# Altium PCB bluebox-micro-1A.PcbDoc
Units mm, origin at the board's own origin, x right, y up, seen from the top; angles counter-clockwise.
Board outline 61.47 x 18.68 mm, 4 copper layers (Top Layer, Internal Plane 1, Mid-Layer 2, Bottom Layer), stack 0.859 mm thick; 97 components, 77 nets, 309 pads, 136 vias.
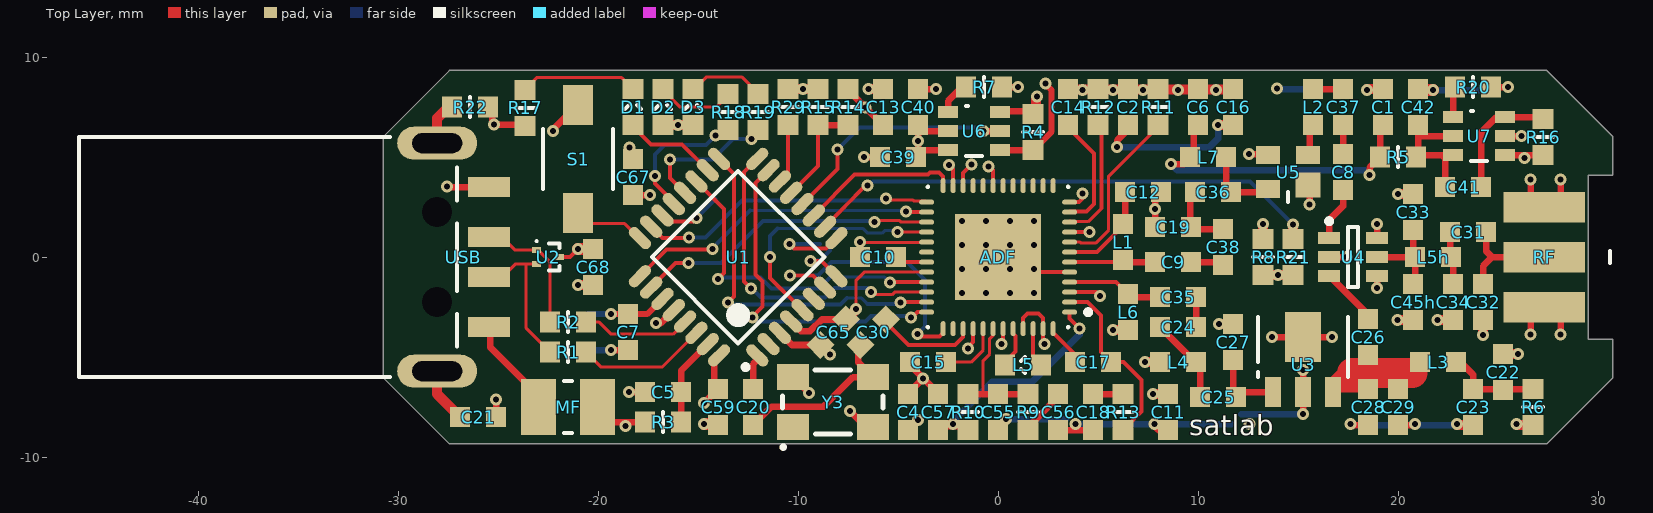
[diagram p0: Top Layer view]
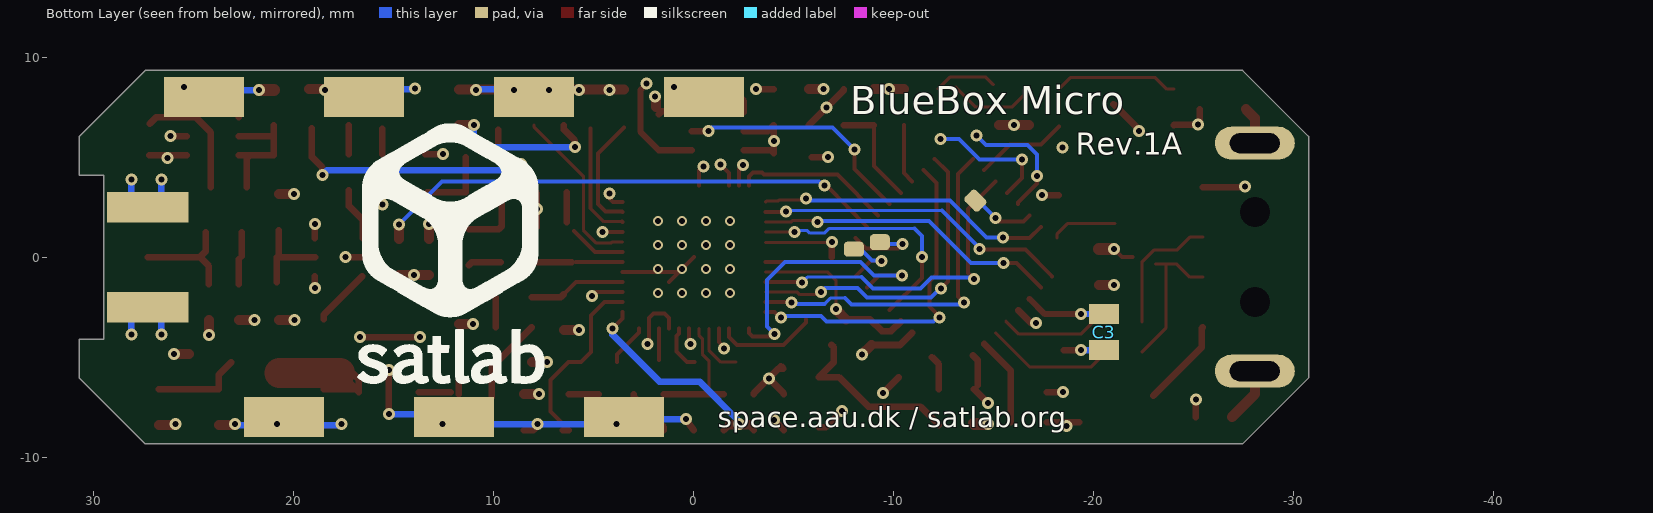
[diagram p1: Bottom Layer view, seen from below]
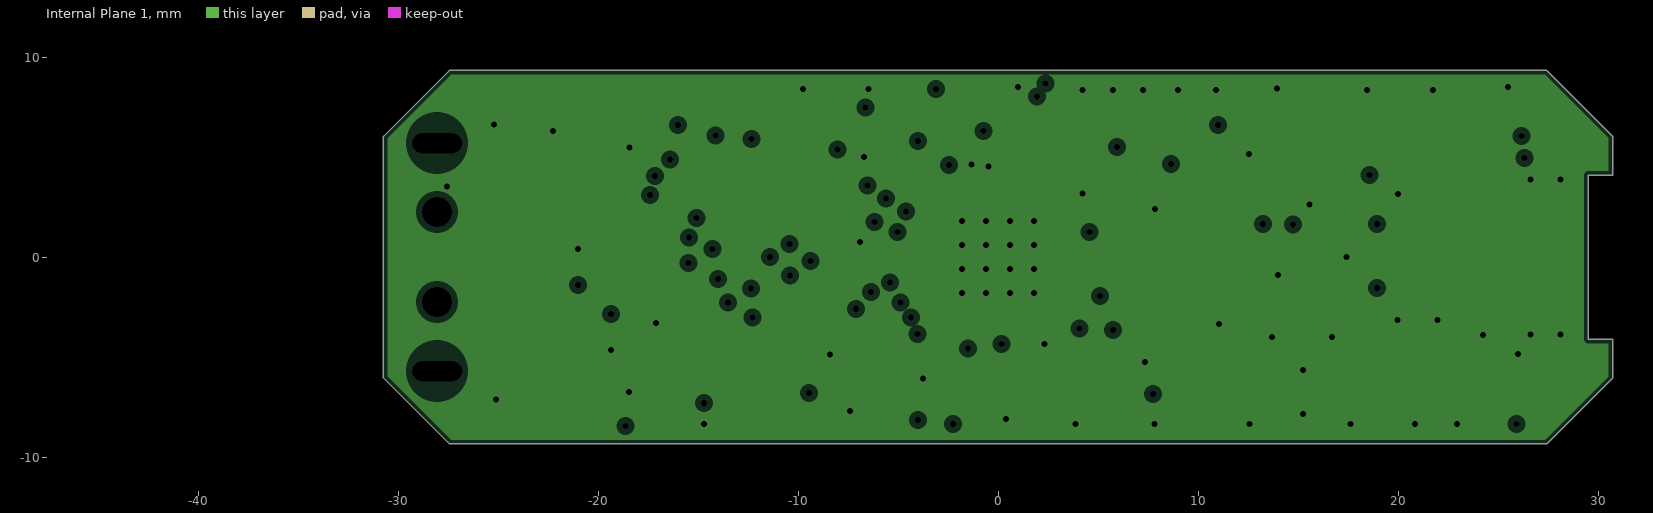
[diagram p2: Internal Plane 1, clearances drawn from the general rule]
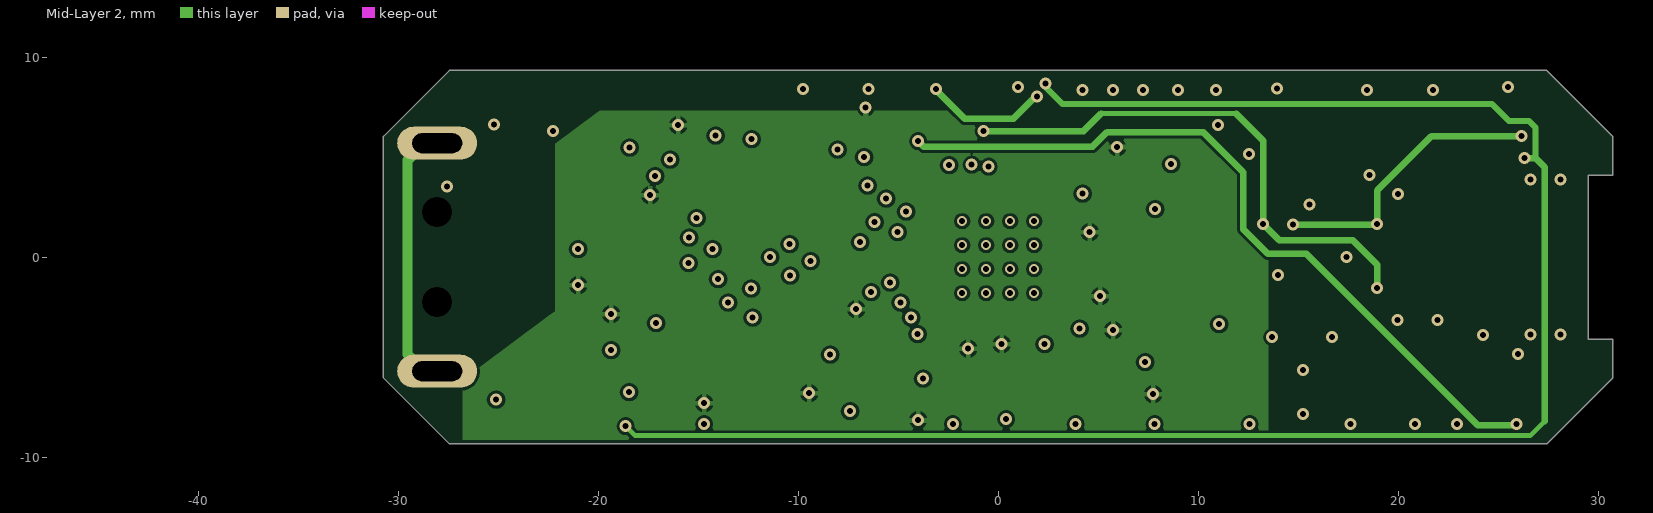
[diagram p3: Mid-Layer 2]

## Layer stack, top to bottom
Top Layer: signal copper 0.0356
Dielectric: core 0.1981, FR-4, Dk 3.6
Internal Plane 1: plane copper 0.0356, net GND
Dielectric: prepreg 0.32, FR-4, Dk 4.8
Mid-Layer 2: signal copper 0.0356
Dielectric: core 0.1981, FR-4, Dk 3.6
Bottom Layer: signal copper 0.0356

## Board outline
-27.434,-9.34 -30.734,-6.04 -30.734,6.04 -30.732,6.04 -27.434,9.338 -27.434,9.34 27.434,9.34 30.734,6.04 30.734,4.1 29.5,4.1 29.5,-4.1 30.734,-4.1 30.734,-6.04 27.434,-9.34

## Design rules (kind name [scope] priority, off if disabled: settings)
Clearance [All] p1: gap=0.15
MinimumSolderMaskSliver [All] p1: minsoldermaskwidth=0.075
PlaneClearance [All] p1: clearance=0.3
PlaneConnect [All] p1: planeconnectstyle=Relief reliefexpansion=0.15 reliefentries=4 reliefconductorwidth=0.254 reliefairgap=0.15
PolygonConnect [All] p1: connectstyle=Relief reliefconductorwidth=0.254 reliefentries=4 polygonreliefangle="90 Angle"
RoutingVias [All] p1: holewidth=0.3 width=0.5 viastyle="Through Hole" minholewidth=0.3 minwidth=0.5 maxholewidth=3 maxwidth=2
SilkscreenOverComponentPads [All] p1: minsilkscreentomaskgap=0.154
SolderMaskExpansion [All] p1: expansion=0.075
Width [All] p1: maxlimit=2 minlimit=0.15 preferedwidth=0.2
24 further rules are at their usual default settings.

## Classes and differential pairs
component class transceiver: ADF C3 C4 C9 C9h C10 C11 C12 C12h C13 C14 C15 C16 C17 C18 C20 C30 C35 C42h C55 C56 C57 C59 L1 L1h L5 L6 R9 R10 R11 R12 R13 Y3
component class mcu: C2 C5 C7 C21 C60 C61 C62 C63 C64 C65 C67 C68 CaSS9 D1 D2 D3 MF Q4 R1 R2 R3 R14 R15 R17 R18 R19 R22 R29 R34 S1 U1 U2 USB Usw9 VR1
component class misc_rf: C1 C6 C8 C19 C22 C23 C24 C25 C26 C27 C28 C29 C31 C32 C33 C34 C36 C37 C38 C39 C40 C41 C42 C45h C? L2 L3 L4 L5h L7 L? Q2 R4 R5 R6 R7 R8 R16 R20 R21 R? RF U3 U4 U5 U6 U7 U?

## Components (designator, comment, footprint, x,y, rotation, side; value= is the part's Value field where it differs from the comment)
ADF "ADF7021" QFN50P700X700X100-48M 0,0 r180 top
C1 "Cap Semi" C06#1 19.25,7.5 r90 top
C2 "Capacitor" C06#1 6.5,7.5 r270 top
C3 "Cap Semi" C06#2 -20.5,-3.75 r90 bottom
C4 "Cap Semi" C06#1 -4.5,-7.75 r270 top
C5 "Cap Semi" C06#1 -16.75,-6.75 r0 top
C6 "Cap Semi" C06#1 10,7.5 r90 top
C7 "Cap Semi" C06#1 -18.5,-3.75 r270 top
C8 "Cap Semi" C06#1 17.25,4.25 r90 top
C9 "Cap Semi" C06#1 8.75,-0.25 r180 top
C10 "Cap Semi" C06#1 -6,0 r0 top
C11 "Cap Semi" C06#1 8.5,-7.75 r90 top
C12 "Cap Semi" C06#1 7.25,3.25 r180 top
C13 "Cap Semi" C06#1 -5.75,7.5 r270 top
C14 "Cap Semi" C06#1 3.5,7.5 r270 top
C15 "Cap Semi" C06#1 -3.5,-5.25 r0 top
C16 "Cap Semi" C06#1 11.75,7.5 r270 top
C17 "Cap Semi" C06#1 4.75,-5.25 r180 top
C18 "Cap Semi" C06#1 4.75,-7.75 r270 top
C19 "Cap Semi" C06#1 8.75,1.5 r180 top
C20 "Cap Semi" C06#1 -12.25,-7.5 r90 top
C21 "Cap Semi" C06#1 -26,-8 r0 top
C22 "Cap Semi" C06#1 25.25,-5.75 r90 top
C23 "Cap Semi" C06#1 23.75,-7.5 r270 top
C24 "Cap Semi" C06#1 9,-3.5 r180 top
C25 "Cap Semi" C06#1 11,-7 r0 top
C26 "Cap Semi" C06#1 18.5,-4 r270 top
C27 "Cap Semi" C06#1 11.75,-4.25 r270 top
C28 "Cap Semi" C06#1 18.5,-7.5 r270 top
C29 "Cap Semi" C06#1 20,-7.5 r270 top
C30 "Cap Semi" C06#1 -6.25,-3.75 r45 top
C31 "Capacitor" C06#1 23.5,1.25 r180 top
C32 "Capacitor" C06#1 24.25,-2.25 r90 top
C33 "Cap Semi" C06#1 20.75,2.25 r90 top
C34 "Cap Semi" C06#1 22.75,-2.25 r270 top
C35 "Cap Semi" C06#1 9,-2 r0 top
C36 "Cap Semi" C06#1 10.75,3.25 r0 top
C37 "Cap Semi" C06#1 17.25,7.5 r90 top
C38 "Cap Semi" C06#1 11.25,0.5 r270 top
C39 "Capacitor" C06#1 -5,5 r0 top
C40 "Capacitor" C06#1 -4,7.5 r90 top
C41 "Capacitor" C06#1 23.25,3.5 r0 top
C42 "Capacitor" C06#1 21,7.5 r270 top
C45h "Cap Semi" C06#1 20.75,-2.25 r90 top
C55 "Cap Semi" C06#1 0,-7.75 r90 top
C56 "Cap Semi" C06#1 3,-7.75 r90 top
C57 "Cap Semi" C06#1 -3,-7.75 r270 top
C59 "Cap Semi" C06#1 -14,-7.5 r90 top
C65 "Capacitor" C06#1 -8.25,-3.75 r45 top
C67 "Capacitor" C06#1 -18.25,4 r270 top
C68 "Capacitor" C06#1 -20.25,-0.5 r270 top
D1 "LED" L06 -18.25,7.5 r90 top
D2 "LED" L06 -16.75,7.5 r90 top
D3 "LED" L06 -15.25,7.5 r90 top
L1 "Inductor" C06#1 6.25,0.75 r270 top
L2 "Inductor" C06#1 15.75,7.5 r90 top
L3 "Inductor" C06#1 22,-5.25 r0 top
L4 "Inductor" C06#1 9,-5.25 r0 top
L5 "Inductor" L06 1.245,-5.385 r180 top
L5h "Inductor" C06#1 21.75,0 r0 top
L6 "Inductor" C06#1 6.5,-2.75 r270 top
L7 "Inductor" C06#1 10.5,5 r180 top
MF "CapacitorBig" C1210 -21.5,-7.5 r180 top
R1 "Resistor" R06 -21.5,-4.75 r180 top
R2 "Resistor" R06 -21.5,-3.25 r0 top
R3 "Resistor" R06 -16.75,-8.25 r0 top
R4 "Resistor" R06 1.75,6.25 r270 top
R5 "Resistor" R06 20,5 r0 top
R6 "Resistor" R06 26.75,-7.5 r270 top
R7 "Resistor" R06 -0.7,8.5 r180 top
R8 "Resistor" R06 13.25,0 r90 top
R9 "Res Semi" R06 1.5,-7.75 r90 top
R10 "Res Semi" R06 -1.5,-7.75 r90 top
R11 "Res Semi" R06 8,7.5 r90 top
R12 "Res Semi" R06 5,7.5 r270 top
R13 "Res Semi" R06 6.25,-7.75 r90 top
R14 "Resistor" R06 -7.5,7.5 r90 top
R15 "Resistor" R06 -9,7.5 r270 top
R16 "Resistor" R06 27.25,6 r270 top
R17 "Resistor" R06 -23.647,7.468 r90 top
R18 "Resistor" R06 -13.5,7.25 r90 top
R19 "Resistor" R06 -12,7.25 r90 top
R20 "Resistor" R06 23.75,8.5 r180 top
R21 "Resistor" R06 14.75,0 r90 top
R22 "Resistor" R06 -26.4,7.5 r0 top
R29 "Resistor" R06 -10.5,7.5 r270 top
RF "50 Ohm - Linx CONSMA003.062" SMA-EGDE 29.3,0 r0 top
S1 "434123050816" spsd-raised -21,4.9 r270 top
U1 "ATmega32U2-AU" 32A_L -13,0 r135 top
U2 "TPD2EUSB30ADRTR" DRT3 -22.5,0 r270 top
U3 "MGA-31589" SOT-223B-SMALL 15.25,-4.5 r0 top
U4 "AS193-73" SOT95P280X145-6N 17.75,0 r0 top
U5 "MBC13916" MBC13916 14.5,4.25 r90 top
U6 "FDC6329L" SSOT-6 -2.5,7.25 r0 top
U7 "FDC6329L" SSOT-6 22.75,7 r0 top
USB "1470695-2" 1470695A -30.75,0 r180 top
Y3 "FOX924B" FOX924 -10.25,-6 r0 top

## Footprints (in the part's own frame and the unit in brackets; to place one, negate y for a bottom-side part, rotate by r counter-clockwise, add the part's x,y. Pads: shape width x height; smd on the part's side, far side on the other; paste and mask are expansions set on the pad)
32A_L [mm] "Thin QFP, 32-Leads, Body 7x7mm, Pitch 0.8mm, IPC High Density"
  oval 1.35x0.55 smd: 1(-4.15,2.8) 2(-4.15,2) 3(-4.15,1.2) 4(-4.15,0.4) 5(-4.15,-0.4) 6(-4.15,-1.2) 7(-4.15,-2) 8(-4.15,-2.8) 17(4.15,-2.8) 18(4.15,-2) 19(4.15,-1.2) 20(4.15,-0.4) 21(4.15,0.4) 22(4.15,1.2) 23(4.15,2) 24(4.15,2.8)
  oval 0.55x1.35 smd: 9(-2.8,-4.15) 10(-2,-4.15) 11(-1.2,-4.15) 12(-0.4,-4.15) 13(0.4,-4.15) 14(1.2,-4.15) 15(2,-4.15) 16(2.8,-4.15) 25(2.8,4.15) 26(2,4.15) 27(1.2,4.15) 28(0.4,4.15) 29(-0.4,4.15) 30(-1.2,4.15) 31(-2,4.15) 32(-2.8,4.15)
  silkscreen extent -4.27,-3.05 3.05,3.75, body extent -3.5,-3.5 3.5,3.5, height 1.2
1470695A [mm] "Connector; USB1.1, Type A, SM; 4 Position; Right Angle"
  rect 2.1x1 smd: 1(-5.3,3.5) 2(-5.3,1) 3(-5.3,-1) 4(-5.3,-3.5)
  oval 4x1.65 hole 1 slot 2.5 at 0 deg: 5(-2.7,-5.7) 6(-2.7,5.7)
  round 1.2 hole 1.5 unplated: MH1(-2.7,-2.25) MH2(-2.7,2.25)
  silkscreen extent -3.7,-6 15.2,6
C06#1 [mm] "Chip Capacitor, 2-Leads, Body 1.6x0.8mm, IPC Low Density"
  rect 1x1 smd: 1(-0.9,0) 2(0.9,0)
  body extent -0.8,-0.41 0.8,0.41, height 0.82
C06#2 [mm] "Chip Capacitor, 2-Leads, Body 1.6x0.8mm, IPC Low Density"
  rect 1x1.5 smd: 1(-0.9,0) 2(0.9,0)
  body extent -0.8,-0.41 0.8,0.41, height 0.82
C1210 [mm] "Chip Capacitor, 2-Leads, Body 3.2x2.5mm, IPC Low Density"
  rect 1.75x2.8 smd: 1(-1.475,0) 2(1.475,0)
  silkscreen extent -0.2,-1.3 0.2,1.3, body extent -1.75,-1.35 1.75,1.35, height 2.7
DRT3 [mm] "SOTFL, 3-Leads, Body 1x1mm (inc leads), Pitch 0.35mm"
  rect 0.3x0.45 smd: 1(-0.35,-0.575) 2(0.35,-0.575) 3(0,0.575)
  silkscreen extent -0.85,-0.62 0.67,0.58, body extent -0.52,-0.42 0.52,0.42, height 0.5
FOX924 [mm]
  rect 1.6x1.3 smd: 1(0,-2.5) 2(4,-2.5) 3(4,0) 4(0,0)
  silkscreen extent -0.56,-3.56 4.5,0.35, body extent -0.53,-2.83 4.5,0.35, height 1.5
L06 [mm] "Chip LED, 2-Leads, Body 1.6x0.8mm, IPC Low Density"
  rect 1x1.05 smd: 1(-0.9,0) 2(0.9,0)
  silkscreen extent -0.1,-0.4 0.1,0.4, body extent -0.85,-0.45 0.85,0.45, height 0.9
MBC13916 [mm] "SOT-143; 4 Leads; FOR LNA"
  rect 1.25x1.25 smd: 1(-0.65,-1)
  rect 0.9x1.2 smd: 2(0.85,-1) 3(0.85,1) 4(-0.85,1)
  silkscreen extent -1.5,0 -1,0
QFN50P700X700X100-48M [mm] "QFN, 48-Leads, Body 7,0x7,0mm (max), Pitch 0,50mm, IPC Low Density"
  oval 0.75x0.25 smd mask+0.154: 1(-3.575,2.75) 2(-3.575,2.25) 3(-3.575,1.75) 4(-3.575,1.25) 5(-3.575,0.75) 6(-3.575,0.25) 7(-3.575,-0.25) 8(-3.575,-0.75) 9(-3.575,-1.25) 10(-3.575,-1.75) 11(-3.575,-2.25) 12(-3.575,-2.75) 25(3.575,-2.75) 26(3.575,-2.25) 27(3.575,-1.75) 28(3.575,-1.25) 29(3.575,-0.75) 30(3.575,-0.25) 31(3.575,0.25) 32(3.575,0.75) 33(3.575,1.25) 34(3.575,1.75) 35(3.575,2.25) 36(3.575,2.75)
  oval 0.25x0.75 smd mask+0.154: 13(-2.75,-3.575) 14(-2.25,-3.575) 15(-1.75,-3.575) 16(-1.25,-3.575) 17(-0.75,-3.575) 18(-0.25,-3.575) 19(0.25,-3.575) 20(0.75,-3.575) 21(1.25,-3.575) 22(1.75,-3.575) 23(2.25,-3.575) 24(2.75,-3.575) 37(2.75,3.575) 38(2.25,3.575) 39(1.75,3.575) 40(1.25,3.575) 41(0.75,3.575) 42(0.25,3.575) 43(-0.25,3.575) 44(-0.75,3.575) 45(-1.25,3.575) 46(-1.75,3.575) 47(-2.25,3.575) 48(-2.75,3.575)
  rect 4.3x4.3 smd mask+0.154: 49(0,0)
  silkscreen extent -4.62,-3.53 3.53,3.52, body extent -3.5,-3.5 3.5,3.5, height 1
R06 [mm] "Chip Resistor, 2-Leads, Body 1.6x0.8mm, IPC Low Density"
  rect 1x1.05 smd: 1(-0.9,0) 2(0.9,0)
  silkscreen extent 0,-0.5 0,0.5, body extent -0.8,-0.4 0.8,0.4, height 0.55
SMA-EGDE [mm] "Linx CONSMA003.062"
  rect 4.06x1.52 smd: 1(-2,-2.5) 1(-2,2.5) 2(-2,0)
  rect 4.06x1.52 smd far side: 1(-2,-2.5) 1(-2,2.5)
  silkscreen extent 1.3,-0.3 1.3,0.3
SOT95P280X145-6N [mm] "SOT23, 6-Leads, Body 3,0x3,0mm (max), Pitch 0,95mm, IPC Medium Density"
  rect 1.1x0.6 smd: 1(-1.2,0.95) 2(-1.2,0) 3(-1.2,-0.95) 4(1.2,-0.95) 5(1.2,0) 6(1.2,0.95)
  silkscreen extent -1.32,-1.5 0.25,1.92, body extent -0.87,-1.52 0.87,1.53, height 1.45
SOT-223B-SMALL [mm] "used for PA in bluebox micro"
  rect 0.8x1.5 smd: 1(-1.5,-2.25) 2(0,-2.25) 3(1.5,-2.25)
  rect 1.8x2.5 smd: 4(0,0.5)
  silkscreen extent -2.25,-1.5 2.25,1.5
spsd-raised [mm] "WURTH ELEKTRONIK - 434123050816 - SWITCH, 160GF, 6X3.5X5MM, BLK, J-BEND"
  rect 2x1.5 smd: 1(2.7,0) 2(-2.7,0)
  silkscreen extent -1.5,-1.75 1.5,1.75
SSOT-6 [mm]
  rect 1x0.6 smd: 1(0,0) 2(0,-0.95) 3(0,-1.9) 4(2.6,-1.9) 5(2.6,-0.95) 6(2.6,0)
  silkscreen extent 0.9,-2.2 1.7,0.3

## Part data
ADF: "ADF7021 transceiver"
C1 C3 C4 C5 C6 C7 C8 C9 C10 C11 C12 C13 C14 C15 C16 C17 C18 C19 C20 C21 C22 C23 C24 C25 C26 C27 C28 C29 C30 C33 C34 C35 C36 C37 C38 C45h C55 C56 C57 C59: "Capacitor (Semiconductor SIM Model)"
C2 C31 C32 C39 C40 C41 C42 C65 C67 C68: "Capacitor, standard"
D1 D2 D3: "Typical RED GaAs LED"
MF: "Capacitor for PRU etc."
R9 R10 R11 R12 R13: "Semiconductor Resistor"
RF: library part SMA_BOARD_EGDE, "Linx CONSMA003.062  -  SMA Female Edge Mount for 1.6 mm PCB"
S1: library part spsd-raised, "Switch, Subminiature SMT, WURTH ELEKTRONIK - 434123050816 - SWITCH, 160GF, 6X3.5X5MM, BLK, J-BEND"
U1: "8-bit AVR Microcontroller, 2.7-5.5V, 32KB Flash, 1KB EEPROM, 1KB SRAM, 32-pin TQFP, Industrial Grade (-40°C to 85°C)"
U2: "ESD / Surge Solution for High Speed, Low Voltage Interface, 2 Channels, -40 to +85 degC, 3-pin SOT (DRT), Green (RoHS & no Sb/Br)"
U3: "0.5 W High Gain Driver Amplifier"
U4: "PHEMT GaAs IC High-Linearity 3 V  Control SPDT Switch 0.1–2.5 GHz"
U6 U7: "Integrated Load Switch"
USB: "USB 1.1, Right Angle, SMT, A Type, Plug, 4 Position, Natural"
Y3: "FOX924B TCXO 19.44 MHz"

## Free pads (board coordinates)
  rrect50% 1x0.8 smd far side rot 45: 0(-14.075,2.825)
  rrect50% 1x0.8 smd far side: 0(-9.3,0.75)
  rect 4x2 smd far side: 0(-0.5,8) 0(3.5,-8) 0(8,8) 0(12,-8) 0(16.5,8) 0(20.5,-8) 0(24.5,8)
  rrect50% 1x0.75 smd far side: 1(-8,0.4)

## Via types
v1: diameter 0.6, hole 0.3, Top Layer to Bottom Layer, 43 vias
v2: diameter 0.6, hole 0.3, Top Layer to Bottom Layer, tented top, 34 vias
v3: diameter 0.6, hole 0.3, Top Layer to Bottom Layer, tented bottom, 22 vias
v4: diameter 0.6, hole 0.3, Top Layer to Bottom Layer, tented both sides, 21 vias
v5: diameter 0.5, hole 0.3, Top Layer to Bottom Layer, tented top, 16 vias

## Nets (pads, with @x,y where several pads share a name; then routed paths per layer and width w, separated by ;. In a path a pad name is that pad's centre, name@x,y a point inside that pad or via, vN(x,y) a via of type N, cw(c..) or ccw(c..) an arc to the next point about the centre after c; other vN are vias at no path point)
C-RX: R21.2 U1.10 U4.6 U7.5 | length 41.7
  Top Layer w0.2: U1.10 -6.647,3.55 v1@-6.5,3.55
  Top Layer w0.34: U4.6 v3(18.95,1.65) ; U7.5 v2(26.175,6.05)
  Top Layer w0.5: R21.2 v3(14.75,1.625)
  Mid-Layer 2 w0.34: v3(14.75,1.625) v3@18.925,1.625 ; v3(18.95,1.65) 18.95,3.325 21.675,6.05 v2(26.175,6.05)
  Bottom Layer w0.2: v1@-6.5,3.55 -6.35,3.675 -6.25,3.775 12.6,3.775 v3(14.75,1.625)
  other v1: -6.525,3.575
C-TX: R8.2 U1.12 U4.4 U6.5 | length 40.2
  Top Layer w0.2: U1.12 -8.025,4.409 v1(-8.025,5.375)
  Top Layer w0.34: v2(-0.725,6.3) U6.5 ; v4(18.95,-1.55) U4.4
  Top Layer w0.5: R8.2 v3(13.25,1.65)
  Mid-Layer 2 w0.25: 5.15,7.175 11.9,7.175
  Mid-Layer 2 w0.34: v2(-0.725,6.3) 4.275,6.3 5.15,7.175 ; 11.9,7.175 13.25,5.825 v3(13.25,1.65) 14.05,0.85 17.725,0.85 18.95,-0.375 v4(18.95,-1.55)
  Bottom Layer w0.2: v1(-8.025,5.375) -6.925,6.475 -0.9,6.475 v2(-0.725,6.3)
CE: ADF.24 U1.11 | length 8.3
  Top Layer w0.2: U1.11 -7.178,4.125 -3.5,4.125 -3.4,4.225 -2.95,4.225 -2.75,4.025 ADF.24 -2.75,4
CLK_OUT: ADF.36 U1.15 | length 16.9
  Top Layer w0.2: v1@-12.25,-2.875 -12.175,-2.875 -11.775,-2.475 -11.775,-1.225 -12.125,-0.875 -12.125,3.703 U1.15 ; v2@-4.35,-3 -4.275,-3 -4.025,-2.75 ADF.36
  Bottom Layer w0.2: v1@-12.275,-2.9 -12.275,-2.925 -11.975,-3.225 -6.625,-3.225 -6.35,-2.95 v2@-4.375,-2.95
  other v1: -12.275,-3.025
  other v2: -4.35,-3.025
CPOUT: ADF.42 C55.2 R9.2 R10.2 | length 6.5
  Top Layer w0.15: -0.75,-6.85 -0.75,-5.175 -0.425,-4.85 -0.425,-4.075 -0.25,-3.9 ADF.42
  Top Layer w0.34: R10.2 R9.2
CREG3: ADF.41 C15.2 | length 2.7
  Top Layer w0.15: -2.1,-5.25 -1.35,-5.25 -0.75,-4.65 ADF.41
D+: R2.1 U2.1 USB.3 | length 6.6
  Top Layer w0.15: USB.3 -24.8,1 -24.15,0.35 -23,0.35 -22.4,-0.25 R2.1
D-: R1.2 U2.2 USB.2 | length 7.5
  Top Layer w0.15: USB.2 -24.8,-1 -24.15,-0.35 U2.2 ; -23.6,-0.35 -23.6,-3.55 R1.2
DATA_CLK: ADF.35 U1.17 | length 17.9
  Top Layer w0.2: U1.17 -13.2,4.16 -13.2,-1.975 v1(-13.5,-2.275) ; v2@-4.925,-2.25 ADF.35
  Bottom Layer w0.15: -7.55,-2.05 -6.825,-2.05 -6.525,-2.35
  Bottom Layer w0.2: v1(-13.5,-2.275) -13.4,-2.375 -7.875,-2.375 -7.55,-2.05 ; -6.525,-2.35 -5,-2.35 v2@-4.9,-2.25
  other v2: -4.875,-2.275
DATA_IO: ADF.34 U1.16 | length 16.2
  Top Layer w0.15: v1@-6.325,-1.925 -6.275,-1.875 -5.3,-1.875 -5.175,-1.75 ADF.34
  Top Layer w0.2: v1(-12.35,-1.575) -12.7,-1.225 -12.7,4.26 U1.16
  Bottom Layer w0.2: v1(-12.35,-1.575) -12.325,-1.55 -12.275,-1.55 -12.275,-1.6 -11.85,-2.025 -8.656,-2.025 -8.181,-1.55 -6.55,-1.55 v1(-6.35,-1.75)
GND: ADF.5 ADF.12 ADF.19 ADF.22 ADF.29 ADF.45 ADF.47 ADF.49 C1.2 C2.1 C3.1 C4.1 C5.1 C6.2 C7.2 C10.1 C11.1 C12.1 C13.1 C14.1 C15.1 C16.1 C18.2 C19.2 C21.2 C22.2 C23.2 C27.1 C28.2 C29.2 C32.1 C33.2 C34.2 C39.1 C42.1 C45h.1 C55.1 C56.1 C57.1 C59.1 C65.1 C67.1 C68.1 L4.1 pad.0@3.5,-8 pad.0@8,8 pad.0@12,-8 pad.0@16.5,8 pad.0@20.5,-8 pad.0@24.5,8 pad.0@-0.5,8 R7.1 R8.1 R11.2 R12.1 R15.1 R17.1 R20.1 R21.1 R22.2 R29.1 RF.1 S1.2 U1.3 U1.28 U2.3 U3.2 U3.4 U4.2 U5.1 U5.3 USB.4 Y3.2 | length 106.9
  Top Layer w0.15: v2@-6.9,0.725 ADF.29@-3.575,0.725
  Top Layer w0.2: U2.3 -21.4,0 v2(-21,0.4) ; ADF.22 -1.75,4.2 v1(-1.325,4.625) ; v1@-0.4,4.5 -0.25,4.35 ADF.19 ; ADF.49 ADF.49@1.25,-1.25 ; ADF.49@0.75,-0.75 ADF.5 ; ADF.45 1.25,-3.05 1.475,-2.825 2.025,-2.825 2.25,-3.05 ADF.47 v2@2.25,-4.325 ; ADF.12 4.05,2.75 4.275,2.975 v2@4.275,3.15
  Top Layer w0.34: v4@-27.525,3.5 USB.4 ; R22.2@-25.3,7.4 -25.3,6.7 -25.225,6.625 v2(-25.2,6.625) -24.025,6.625 R17.1@-24,6.6 ; C21.2 v2@-25.1,-7.15 ; v1(-22.25,6.3) -22.225,6.4 S1.2@-20.975,7.65 ; v2(-19.35,-4.65) C7.2 ; v2(-18.45,-6.75) C5.1 ; v1(-17.1,-3.3) -16.866,-3.3 U1.28 ; U1.3 -10.311,-4.386 C65.1 ; v4(-7.4,-7.7) -6.6,-8.5 Y3.2 ; C10.1 v2(-6.9,0.75) ; v2(-6.7,5) C39.1 ; C4.1 -4.5,-6.825 v2(-3.75,-6.075) ; C15.1@-4.35,-5.45 -4.475,-5.575 -4.225,-5.575 -3,-6.8 C57.1 ; C55.1 v4(0.4,-8.1) ; R7.1 v2(1,8.5) ; C56.1 C18.2 ; v4@7.8,-8.425 8.025,-8.65 C11.1 ; C19.2 7.85,3.2 C12.1@7.9,3.25 ; v3(12.55,5.15) U5.3@13.425,5.15 ; v3(13.7,-4) U3.4 v3(16.7,-4) ; v3(15.25,-7.85) U3.2 v3(15.25,-5.65) ; v3(15.575,2.625) U5.1@15.575,3.55 ; U4.2 v4(17.425,0) ; v3@17.625,-8.4 C28.2 ; C29.2 v3@20.85,-8.4 ; R20.1 v1(25.5,8.5) ; v1(26.625,-3.875) RF.1@26.625,-3.175 ; RF.1@26.625,3.175 v1(26.625,3.875) ; v1(28.125,-3.875) RF.1@28.125,-3.2 ; RF.1@28.125,3.025 v1(28.125,3.875)
  Top Layer w0.5: v4@-14.7,-8.4 C59.1 ; v4@-14.65,-8.3 C59.1@-13.95,-8.3 ; R29.1 R15.1 ; C65.1 v2(-8.4,-4.873) ; v2@-6.5,8.4 C13.1 ; C14.1@3.5,8.375 C16.1@11.75,8.375 ; v4(7.35,-5.25) L4.1 ; v4(11.05,-3.35) C27.1 ; R8.1 R21.1 ; v1@18.45,8.4 C1.2 ; v3(19.975,-3.15) C45h.1 ; v3(20,3.15) C33.2 ; v3(21.975,-3.15) C34.2 ; v3@22.95,-8.4 C23.2 ; v1(24.25,-3.9) C32.1 ; C22.2 v1(26,-4.85)
  Top Layer w0.6: v2(-21,0.4) C68.1 ; C42.1@21,8.35 v1(21.75,8.35)
  Bottom Layer w0.34: C3.1 v2(-19.35,-4.65) ; v4(0.4,-8.1) pad.0@3.4,-8.1 ; pad.0@3.85,-8.35 v4(7.825,-8.35) pad.0@11.65,-8.35 ; v1@5.75,8.4 pad.0@7.6,8.4 ; pad.0@8.4,8.4 v1@10.9,8.4 ; pad.0@12.15,-7.85 v3(15.25,-7.85) ; v1@14,8.4 pad.0@16.1,8.4 ; v3@17.625,-8.4 pad.0@20.1,-8.4 ; pad.0@20.9,-8.4 v3@22.95,-8.4 ; v1(21.75,8.35) pad.0@24.125,8.35 ; v1(26.625,-3.875) RF.1@26.625,-3.175 ; RF.1@26.625,3.175 v1(26.625,3.875) ; v1(28.125,-3.875) RF.1@28.125,-2.85 ; RF.1@28.125,2.85 v1(28.125,3.875)
  other v1: -0.475,4.525 4.225,8.35 5.75,8.35 7.25,8.35 10.9,8.35 18.45,8.35 13.95,8.425
  other v2: -25.1,-7.125 2.325,-4.35 4.225,3.175 -18.425,5.475 9,8.35 -6.475,8.4
  other v3: 12.575,-8.35 17.625,-8.35 20.85,-8.35 22.95,-8.35
  other v4: -14.7,-8.35 3.875,-8.35 14,-0.9 7.85,2.4 -27.55,3.525 -9.75,8.4
  other v5: -1.8,-1.8 -0.6,-1.8 0.6,-1.8 1.8,-1.8 -1.8,-0.6 -0.6,-0.6 0.6,-0.6 1.8,-0.6 -1.8,0.6 -0.6,0.6 0.6,0.6 1.8,0.6 -1.8,1.8 -0.6,1.8 0.6,1.8 1.8,1.8
HWB: R14.1 R15.2 U1.13 | length 5.4
  Top Layer w0.2: U1.13 -9,4.566 R15.2
  Top Layer w0.34: R15.2 R14.1
L1: ADF.46 L5.1 | length 1.6
  Top Layer w0.2: L5.1@1.75,-5.15 ADF.46
L2: ADF.44 L5.2 | length 2.3
  Top Layer w0.2: L5.2@-0.025,-5.25 0.35,-5.25 0.875,-4.725 0.875,-3.95 0.75,-3.825 ADF.44
LED_P: R19.1 U1.20 | length 6.5
  Top Layer w0.2: v1(-16.4,4.875) -16.4,3.966 U1.20
  Bottom Layer w0.2: v1(-16.4,4.875) -14.275,4.875 -13.25,5.9 v2(-12.325,5.9)
LED_R: R18.1 U1.21 | length 6.3
  Top Layer w0.2: v1(-17.15,4.05) -17.15,3.675 -16.217,2.742 U1.21
  Bottom Layer w0.2: v1(-17.15,4.05) -17.15,5.125 -16.675,5.6 -14.6,5.6 v2(-14.125,6.075)
LED_T: D1.1 U1.18 | length 4.6
  Top Layer w0.2: D1.1@-18.25,6.525 -17.35,5.625 -15.797,5.625 U1.18
MUXOUT: ADF.37 U1.7 | length 14.4
  Top Layer w0.2: v3@-10.325,-0.925 -9.247,-0.925 U1.7 ; U1.7@-9.025,-1.15 U1.7@-8.65,-1.525 ; v2@-4.075,-3.825 -3.925,-3.975 -2.925,-3.975 -2.75,-3.8 ADF.37
  Bottom Layer w0.2: v3@-10.375,-0.925 -9,-0.925 -8.325,-0.25 -4.55,-0.25 -3.65,-1.15 -3.65,-3.475 v2(-4.025,-3.85)
  other v3: -10.4,-0.925
NetADF_2: ADF.2 C17.1 R13.1 | length 9.5
  Top Layer w0.2: ADF.2 4.475,-2.25 5.15,-2.925 5.15,-4.75 C17.1 6.275,-5.25 7.175,-6.15 7.175,-7.725 R13.1
  Top Layer w0.34: R13.1 R13.1@6.55,-8.65
NetADF_4: ADF.4 C35.1 L6.1 | length 4.8
  Top Layer w0.2: ADF.4 5.9,-1.25 L6.1
  Top Layer w0.34: L6.1 6.65,-2 C35.1
NetADF_6: ADF.6 C9.2 L1.2 | length 4.1
  Top Layer w0.2: ADF.6 L1.2@5.9,-0.25
  Top Layer w0.34: L1.2@6.1,-0.25 C9.2
NetADF_7: ADF.7 C12.2 L1.1 | length 4.4
  Top Layer w0.2: ADF.7 4.95,0.25 L1.1@6,1.3
  Top Layer w0.34: L1.1@6.35,1.75 C12.2
NetADF_8: ADF.8 R11.1 | length 8.5
  Top Layer w0.15: ADF.8 4.1,0.75 4.15,0.7 4.875,0.7 5.525,1.35 5.525,4.05 8,6.525 R11.1
NetADF_10: ADF.10 R12.2 | length 5.9
  Top Layer w0.15: ADF.10@3.6,1.775 4.5,1.775 5.175,2.45
  Top Layer w0.2: ADF.10 ADF.10@3.6,1.775 ; 5.175,2.45 R12.2@5.175,6.425
NetADF_11: ADF.11 C14.2 | length 5.8
  Top Layer w0.2: C14.2@3.5,6.475 4.8,5.175 4.8,2.65 4.425,2.275 3.6,2.275 ADF.11
NetADF_31: ADF.31 C10.2 | length 1.3
  Top Layer w0.2: C10.2@-4.85,-0.25 ADF.31
NetADF_39: ADF.39 C30.2 | length 5.1
  Top Layer w0.2: C30.2 -5.614,-3.261 -4.475,-4.4 -2.15,-4.4 -1.75,-4 ADF.39
NetADF_48: ADF.48 C17.2 | length 2.1
  Top Layer w0.2: ADF.48 2.75,-3.775 3.85,-4.875 C17.2
NetC1_1: C1.1 C6.1 L7.2 R5.1 | length 15.3
  Top Layer w0.34: v4(8.65,4.65) 9.25,4.65 L7.2 9.775,5.175 C6.1@9.775,6.375 ; v4(18.575,4.1) 18.575,4.475 R5.1 C1.1@19.1,6.45
  Bottom Layer w0.34: v4(8.65,4.65) 8.95,4.35 18.325,4.35 v4(18.575,4.1)
NetC5_2: C5.2 R3.2 U1.31 | length 4.5
  Top Layer w0.34: R3.2 -15.85,-5.678 U1.31
NetC8_2: C8.2 C37.1 | length 1.4
  Top Layer w0.34: C8.2 C37.1
NetC18_1: C18.1 R13.2 | length 1.5
  Top Layer w0.34: C18.1 R13.2
NetC19_1: C19.1 C36.1 C38.1 | length 3.4
  Top Layer w0.34: C36.1@9.6,3.25 9.6,1.55 9.75,1.4 C38.1
NetC20_1: C20.1 C30.1 Y3.3 | length 9
  Top Layer w0.34: C20.1 -11.325,-7.475 -8.725,-7.475 -7.25,-6 Y3.3 -7,-5.25 -7,-4.5 C30.1
NetC21_1: C21.1 R22.1 USB.5 USB.6 | length 18
  Top Layer w0.5: USB.6 -28.05,-6.85 C21.1 ; USB.5 -28.05,6.95 R22.1@-27.6,7.4
  Mid-Layer 2 w0.5: USB.6 -28.7,-5.7 -29.525,-4.875 -29.525,4.85 -28.675,5.7 USB.5
NetC22_1: C22.1 C23.1 L3.2 R6.1 | length 4.6
  Top Layer w0.34: L3.2@23.125,-5.25 23.75,-5.875 C23.1 R6.1
NetC24_2: C24.2 C25.1 L4.2 | length 4.1
  Top Layer w0.34: C24.2 9.85,-5.25 L4.2 ; C25.1 L4.2@10.1,-5.45
NetC25_2: C25.2 C27.2 U3.1 | length 3.3
  Top Layer w0.34: C25.2@11.75,-6.85 C27.2 ; C25.2@12.15,-6.75 U3.1
NetC26_2: C26.2 C28.1 C29.1 L3.1 U3.3 | length 7.7
  Top Layer w0.34: U3.3@16.9,-6.6 C28.1 ; U3.3 16.75,-6.125 17.075,-5.8 17.7,-5.8 U3.3
  Top Layer w1.5: 17.7,-5.8 20.725,-5.8
NetC31_2: C31.2 C34.1 L5h.2 | length 2.4
  Top Layer w0.34: L5h.2@22.6,0.05 C31.2 ; C34.1 L5h.2@22.75,-0.1
NetC33_1: C33.1 C45h.2 L5h.1 U4.5 | length 4.4
  Top Layer w0.34: U4.5@18.925,0 L5h.1 C45h.2@20.85,-1.25 ; L5h.1@20.75,0.1 C33.1
NetC36_2: C36.2 L7.1 U5.4 | length 3.7
  Top Layer w0.34: L7.1 11.4,3.25 U5.4@13.325,3.25
NetC37_2: C37.2 L2.2 | length 1.5
  Top Layer w0.34: L2.2 C37.2
NetC40_2: C40.2 R4.1 U6.6 | length 9.1
  Top Layer w0.34: C40.2 v2(-3.1,8.4) ; U6.6@0.15,7.3 1.6,7.3 R4.1
  Top Layer w0.5: R4.1@1.9,7.5 v4@1.9,8
  Mid-Layer 2 w0.34: v2(-3.1,8.4) -3.1,8.35 -1.675,6.925 0.775,6.925 v4@1.8,7.95 ; v4@1.9,7.975 v4@1.9,8
  other v4: 1.95,8.025
NetC41_2: C41.2 R16.1 U7.6 | length 6.2
  Top Layer w0.34: C41.2 24.15,6.225 24.925,7 U7.6 26.875,7 R16.1@27.2,6.675
NetC56_2: C56.2 R9.1 | length 2.4
  Top Layer w0.34: R9.1 1.5,-8.5 3,-7 C56.2
NetD1_2: D1.2 R17.2 | length 6.2
  Top Layer w0.15: R17.2@-24,8.4 -23.65,8.4 -23.075,8.975 -18.825,8.975 D1.2
NetD2_2: D2.2 R18.2 | length 4.4
  Top Layer w0.15: D2.2@-16.5,8.4 -16.5,8.1 -15.9,7.5 -14.1,7.5 R18.2@-13.1,8.5
NetD3_2: D3.2 R19.2 | length 3.2
  Top Layer w0.15: D3.2@-14.975,8.625 -14.6,9 -12.8,9 R19.2@-12.2,8.4
NetL2_1: L2.1 U5.2 | length 1.3
  Top Layer w0.34: U5.2@15.575,5.15 L2.1@15.575,6.425
NetMF_2: MF.2 USB.1 | length 4.5
  Top Layer w0.34: USB.1 -25.4,-3.55 -25.4,-4.5 MF.2@-22.975,-6.925
NetR1_1: R1.1 U1.30 | length 6.5
  Top Layer w0.15: R1.1 -19.85,-5.5 -16.803,-5.5 U1.30
NetR2_2: R2.2 U1.29 | length 5.5
  Top Layer w0.15: R2.2 -19.95,-3.25 -19.35,-3.85 -16.25,-3.85 U1.29@-15.6,-3.2
NetR7_2: R7.2 U6.1 | length 1.3
  Top Layer w0.34: U6.1 -2.5,7.8 R7.2@-2,8.3
NetR20_2: R20.2 U7.1 | length 1.4
  Top Layer w0.34: U7.1 R20.2@22.75,8.4
NetR29_2: R29.2 U1.14 | length 3
  Top Layer w0.2: U1.14 -10.5,4.197 R29.2
NetS1_1: S1.1 U1.24 | length 3.3
  Top Layer w0.15: S1.1@-21.05,1.675 -18.675,1.675 -18.164,1.164 U1.24@-18.164,0.955
PA_IN: C24.1 C35.2 | length 1.5
  Top Layer w0.34: C24.1 C35.2
PA_OUT: C26.1 U4.3 | length 2.9
  Top Layer w0.34: U4.3@16.575,-0.95 18.5,-2.875 C26.1
RF: C31.1 C32.2 RF.2 | length 5.5
  Top Layer w0.34: C32.2 24.25,-0.45 24.7,0 ; C31.1 24.4,0.3 24.7,0 ; RF.2 24.7,0
RF_LNA_IN: C8.1 U4.1 | length 2.7
  Top Layer w0.34: U4.1 16.55,1.85 17.25,2.55 C8.1
RF_LNA_OUT: C9.1 C38.2 | length 1.7
  Top Layer w0.34: C9.1 11.1,-0.25 C38.2
SCCLK: ADF.28 U1.5 | length 12.5
  Top Layer w0.15: v1(-5.025,1.25) ADF.28
  Top Layer w0.2: v3@-11.4,0.025 -11.4,-1.034 U1.5
  Bottom Layer w0.15: -11.025,1.425 -6.75,1.425 -6.525,1.2 -5.8,1.2 -5.675,1.325 -5.1,1.325 v1@-5.05,1.275
  Bottom Layer w0.2: v3(-11.4,0) -11.4,1.05 -11.025,1.425
SDATA: ADF.26 U1.25 | length 15.8
  Top Layer w0.2: U1.25 -16.585,0.375 v1@-14.25,0.375 ; v1@-4.6,2.25 ADF.26
  Bottom Layer w0.15: -12.4,2.325 -4.675,2.325 v1@-4.6,2.25
  Bottom Layer w0.2: v1@-14.325,0.4 -12.4,2.325
  other v1: -14.275,0.4 -4.6,2.275
SLE: ADF.25 U1.23 | length 14.5
  Top Layer w0.15: v1@-5.325,2.85 -4.25,2.85 -4.2,2.8 -3.625,2.8 ADF.25
  Top Layer w0.2: U1.23 -16.778,0.95 v1@-15.425,0.95
  Bottom Layer w0.2: v1@-15.438,0.988 -14.637,0.988 -12.8,2.825 -5.8,2.825 v1@-5.675,2.95
  other v1: -15.45,0.975 -5.6,2.925
SREAD: ADF.27 U1.26 | length 15.3
  Top Layer w0.15: v1@-6.1,1.825 -4.925,1.825 -4.85,1.75 ADF.27
  Top Layer w0.2: U1.26 -16.128,-0.3 v1@-15.425,-0.3
  Bottom Layer w0.2: v1@-15.525,-0.3 -13.85,-0.3 -11.75,1.8 v1@-6.125,1.8
  other v1: -15.475,-0.3 -6.175,1.75
SWD: ADF.33 U1.19 | length 16.7
  Top Layer w0.2: U1.19 -13.7,2.397 -13.7,-0.8 v1(-14,-1.1) ; v2@-5.45,-1.25 ADF.33
  Bottom Layer w0.15: -8.375,-1 -5.675,-1 v2@-5.425,-1.25
  Bottom Layer w0.2: v1@-14.075,-1.075 -14.025,-1.025 -11.875,-1.025 -11.325,-1.575 -8.95,-1.575 -8.375,-1
  other v2: -5.4,-1.275
TEST_A: ADF.23 | length 1.2
  Top Layer w0.2: v1@-2.5,4.65 -2.25,4.4 ADF.23
  other v1: -2.45,4.6
TEST_PAD1: pad.1 U1.8 | length 2.8
  Top Layer w0.2: v3(-9.375,-0.2) -8.84,-0.2 U1.8
  Bottom Layer w0.2: v3@-9.375,-0.175 -8.9,-0.175 pad.1@-8.4,0.325
TEST_PAD2: pad.0@-9.3,0.75 U1.9 | length 4.2
  Top Layer w0.2: v3(-10.425,0.65) -10.2,0.425 -8.615,0.425 U1.9
  Bottom Layer w0.2: v3(-10.425,0.65) pad.0@-8.9,0.65
TEST_PAD3: pad.0@-14.075,2.825 U1.22 | length 3.3
  Top Layer w0.2: U1.22 -16.472,1.775 -15.25,1.775 v1(-15.075,1.95)
  Bottom Layer w0.2: v1(-15.075,1.95) pad.0@-14.125,2.9
V_BUS: MF.1 R3.1 R4.2 R16.2 U6.4 U7.4 | length 96.1
  Top Layer w0.3: R4.2 2.675,6.275 2.675,8.35 v1@2.375,8.65
  Top Layer w0.34: MF.1@-19.275,-8.25 R3.1 ; U6.4 R4.2 ; U7.4 R16.2@27.225,5.1
  Mid-Layer 2 w0.25: v4(-18.625,-8.45) -18.15,-8.925 26.6,-8.925 27.325,-8.2
  Mid-Layer 2 w0.3: v1@2.4,8.475 3.225,7.65 24.7,7.65 25.55,6.8 26.55,6.8 26.875,6.475 26.875,4.95
  Mid-Layer 2 w0.34: v2(26.325,4.95) 26.875,4.95 27.325,4.5 27.325,-8.2
  other v1: 2.375,8.675
V_BUS_LNA: C41.1 C42.2 R5.2 U7.2 U7.3 | length 6.6
  Top Layer w0.34: C42.2 21,5.1 U7.3 ; 21.025,6.05 U7.2 ; 22.2,5.1 22.35,4.95 C41.1
V_BUS_PA: C39.2 C40.1 R6.2 U6.2 U6.3 | length 43.5
  Top Layer w0.34: U6.3 -3.85,5.35 -4,5.2 C40.1 -3.7,6.3 U6.2
  Top Layer w0.5: v1@25.925,-8.4 R6.2
  Mid-Layer 2 w0.34: v1(-4,5.8) -3.725,5.525 4.725,5.525 5.45,6.25 10.25,6.25 12.25,4.25 12.25,1.4 13.475,0.175 15.4,0.175 23.975,-8.4 v1@25.925,-8.4
  other v1: 25.925,-8.35
VCC: ADF.3 ADF.9 ADF.32 ADF.40 ADF.43 C2.2 C3.2 C4.2 C7.1 C11.2 C13.2 C16.2 C59.2 C65.2 C67.2 C68.2 D2.1 D3.1 L6.2 R14.2 U1.4 U1.27 U1.32 Y3.4 | length 37.3
  Top Layer w0.15: v2(-7.1,-2.6) -7.1,-1.15 -6.7,-0.75 -5.975,-0.75 ADF.32
  Top Layer w0.2: v2@-1.375,-4.375 -1.25,-4.25 ADF.40 ; v2@0.05,-4.3 0.25,-4.1 ADF.43 ; ADF.3 4.9,-1.75 v1(5.1,-1.95) ; ADF.9 v2(4.575,1.25)
  Top Layer w0.3: v2(-19.35,-2.85) -17.547,-2.85 U1.27
  Top Layer w0.34: C67.2 v2(-17.4,3.1) ; v3(-14.7,-7.3) C59.2 ; C59.2@-14.2,-6.4 -14.2,-5.16 U1.32 ; U1.4 -9.866,-3.7 -9.4,-3.7 -8.814,-3.114 C65.2 ; Y3.4 v2(-9.45,-6.8) ; R14.2 -7.5,8.35 C13.2 ; C65.2@-7.462,-2.963 v2(-7.1,-2.6) ; C4.2 v4(-4,-8.15) ; v1(5.95,5.5) 5.95,5.825 6.5,6.375 C2.2
  Top Layer w0.5: v2(-21,-1.4) C68.2 ; D2.1 D3.1 ; C65.2 v2(-7.1,-2.6) ; v1(5.75,-3.65) L6.2 ; v4(7.75,-6.85) C11.2 ; v4@11.05,6.6 C16.2
  Bottom Layer w0.3: C3.2 v2(-19.35,-2.85)
  Bottom Layer w0.34: v1(5.95,5.5) 10.575,5.5 11,5.925 v4(11,6.6)
  other v2: -1.5,-4.575 0.175,-4.35 -6.625,7.475
  other v4: -16,6.6
VCOIN: ADF.1 C57.2 R10.1 | length 12.2
  Top Layer w0.2: ADF.1 3.575,-3.075 v1(4.075,-3.575)
  Top Layer w0.34: C57.2 -2.8,-8.45 -1.7,-8.45 R10.1 ; C57.2@-2.825,-8.3 R10.1@-1.725,-8.3
  Bottom Layer w0.34: v3@-2.261,-8.204 -0.281,-6.225 1.725,-6.225 4.075,-3.875 v1(4.075,-3.575)
  other v3: -2.261,-8.35
X1: C20.2 U1.1 | length 1.7
  Top Layer w0.34: C20.2 -12.25,-5.35 U1.1@-11.9,-5
pads on no net: ADF.13 ADF.14 ADF.15 ADF.16 ADF.17 ADF.18 ADF.20 ADF.21 ADF.30 ADF.38 U1.2 U1.6 USB.MH1 USB.MH2 Y3.1

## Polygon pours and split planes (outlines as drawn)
VCC on Mid-Layer 2 "b-VCC" (solid, remove dead copper, pour order 1000): -26.775,-9.126 -26.775,-6.133 -22.475,-2.936 -22.15,-2.694 -22.15,5.243 -22.15,5.671 -20,7.269 -19.925,7.325 12.45,7.325 12.55,7.325 13.425,6.674 13.5,6.619 13.5,-9.2
GND on Internal Plane 1 (split plane): 30.524,5.953 30.524,4.31 29.5,4.31 29.446,4.303 29.395,4.282 29.352,4.248 29.318,4.205 29.297,4.154 29.29,4.1 29.29,-4.1 29.297,-4.154 29.318,-4.205 29.352,-4.248 29.395,-4.282 29.446,-4.303 29.5,-4.31 30.524,-4.31 30.524,-5.953 27.347,-9.13 -27.347,-9.13 -30.524,-5.953 -30.524,5.951 -27.345,9.13 27.347,9.13

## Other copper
Top Layer:
  text "S" at -20.355,26.225 h4.79
  text "A" at -17.952,26.225 h4.79
  text "T" at -15.206,26.225 h4.79
  text "L" at -13.147,26.225 h4.79
  text "A" at -10.744,26.225 h4.79
  text "B" at -7.998,26.225 h4.79
  text "." at -5.252,26.225 h4.79
  text "o" at -4.222,26.225 h4.79
  text "r" at -2.162,26.225 h4.79
  text "g" at -0.446,26.225 h4.79
  text "(" at 2.643,26.225 h4.79
  text "C" at 4.016,26.225 h4.79
  text "C" at 7.106,26.225 h4.79
  text "B" at 11.225,26.225 h4.79
  text "Y" at 13.971,26.225 h4.79
  text "-" at 16.717,26.225 h4.79
  text "S" at 18.09,26.225 h4.79
  text "A" at 20.493,26.225 h4.79
  text ")" at 23.239,26.225 h4.79
  text "B" at -20.395,22.875 h2.8
  text "l" at -18.715,22.875 h2.8
  text "u" at -18.043,22.875 h2.8
  text "e" at -16.699,22.875 h2.8
  text "B" at -15.692,22.875 h2.8
  text "o" at -14.012,22.875 h2.8
  text "x" at -12.668,22.875 h2.8
  text "M" at -10.652,22.875 h2.8
  text "i" at -8.636,22.875 h2.8
  text "c" at -7.964,22.875 h2.8
  text "r" at -6.957,22.875 h2.8
  text "o" at -6.285,22.875 h2.8
  text "1" at -4.269,22.875 h2.8
  text "A" at -2.925,22.875 h2.8
  text "h" at -20.096,19.492 h2.8
  text "p" at -18.742,19.492 h2.8
  text "m" at -17.388,19.492 h2.8
  text "@" at -15.696,19.492 h2.8
  text "s" at -13.665,19.492 h2.8
  text "a" at -12.649,19.492 h2.8
  text "t" at -11.634,19.492 h2.8
  text "l" at -10.957,19.492 h2.8
  text "a" at -10.28,19.492 h2.8
  text "b" at -9.264,19.492 h2.8
  text "." at -7.91,19.492 h2.8
  text "o" at -7.233,19.492 h2.8
  text "r" at -5.879,19.492 h2.8
  text "g" at -5.202,19.492 h2.8

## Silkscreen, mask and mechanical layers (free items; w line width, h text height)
Top Overlay:
  text "satlab" at 9.55,-8.9 h1
Bottom Overlay:
  drawing of 1555 lines, arcs and shapes, not listed
  text "BlueBox Micro" at -7.825,7.15 h1.4
  text "Rev.1A" at -19.1,5.125 h1.1
  text "space.aau.dk / satlab.org" at -1.2,-8.5 h1
Mechanical 14:
  lines w0.2: -30.734,6.04 -30.734,-6.04 -27.434,-9.34 27.434,-9.34 30.734,-6.04 30.734,-4.1 29.5,-4.1 29.5,4.1 30.734,4.1 30.734,6.04 27.434,9.34 -27.434,9.34 ; -30.732,6.04 -27.434,9.338

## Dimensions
27.434,9.34 to 27.434,-9.34 on Mechanical 15
-30.734,6.04 to 30.734,4.1 on Mechanical 15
